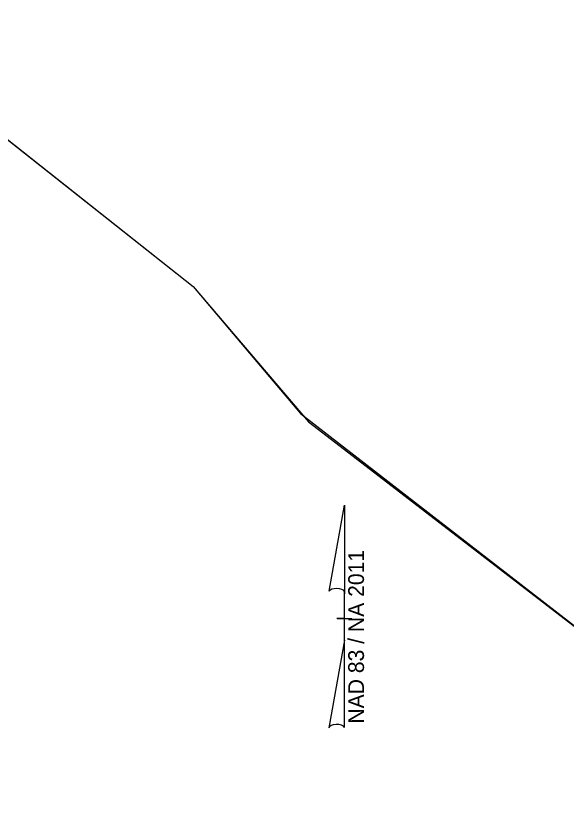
# Model space of a CAD drawing. Extents: x 556999 to 559002, y 505273 to 507273.
# Drawn here: x 558406.6 to 558703.1, y 505917.5 to 506345.6 of the extents above; entities that cross this region are included whole.
import ezdxf

# ---------------------------------------------------------------- set-up
doc = ezdxf.new("R2010")
doc.units = 0
for name, color, linetype in [('Matchline', 7, 'Continuous'), ('Prop Horizontal Alignment Station Label', 7, 'Continuous'), ('Sheet Clip Boundary CELL', 7, 'Continuous')]:
    doc.layers.add(name, color=color, linetype=linetype)

msp = doc.modelspace()

# ---------------------------------------------------------------- linework, layer by layer
at = {"layer": 'Matchline'}
for p, q in [((558069.07, 506542.35), (558502.21, 506199.86)), ((558502.21, 506199.86), (558559.93, 506131.49)), ((558559.93, 506131.49), (558761.1, 505975.77))]:
    msp.add_line(p, q, dxfattribs=at)
at = {"layer": 'Prop Horizontal Alignment Station Label'}
for p, q in [((558575.39, 506035.83), (558583.59, 506082.18)), ((558583.64, 506082.18), (558583.59, 506082.18)), ((558583.64, 506082.18), (558583.59, 506082.18)), ((558583.64, 506082.18), (558583.64, 506034.38)), ((558583.64, 506009.58), (558583.64, 506035.78)), ((558583.64, 506034.38), (558583.64, 506035.73)), ((558579.64, 506021.18), (558579.59, 506021.18)), ((558583.19, 506021.18), (558579.64, 506021.18)), ((558579.69, 506021.18), (558587.69, 506021.18)), ((558583.64, 506009.58), (558575.29, 505962.33)), ((558583.69, 505962.53), (558583.64, 506009.58))]:
    msp.add_line(p, q, dxfattribs=at)
for centre, start_param, end_param in [((558579.52, 506035.34), 0.216388, 2.908219), ((558579.52, 505962.17), 0.201328, 3.141593)]:
    msp.add_ellipse(centre, major_axis=(4.23, -0.03), ratio=0.461098, start_param=start_param, end_param=end_param, dxfattribs=at)
at = {"layer": 'Sheet Clip Boundary CELL'}
msp.add_lwpolyline([(558069.07, 506542.35), (558502.21, 506199.86), (558564.29, 506127.01), (558761.1, 505975.77), (558323.19, 505407.07), (558300.81, 505488.36), (558208.66, 505547.92), (558125.54, 505588.21), (558099.51, 505637.12), (558051.88, 505660.91), (558034.88, 505701.52), (557812.51, 505806.82), (557792.13, 505912.23), (557814.64, 506029.85), (557725.94, 506096.17), (557744.19, 506089.08), (557749.43, 506157.45), (557759.11, 506179.01), (557817.46, 506256.09), (557969.3, 506353.49), (557953.99, 506367.89), (557981.23, 506420.97), (558000.13, 506451.2)], close=True, dxfattribs=at)

# ---------------------------------------------------------------- texts
at = {"layer": 'Prop Horizontal Alignment Station Label'}
msp.add_text('NAD 83 / NA 2011', height=8.5, rotation=90, dxfattribs=at).set_placement((558594.16, 505964.59))

doc.saveas('drawing.dxf')
